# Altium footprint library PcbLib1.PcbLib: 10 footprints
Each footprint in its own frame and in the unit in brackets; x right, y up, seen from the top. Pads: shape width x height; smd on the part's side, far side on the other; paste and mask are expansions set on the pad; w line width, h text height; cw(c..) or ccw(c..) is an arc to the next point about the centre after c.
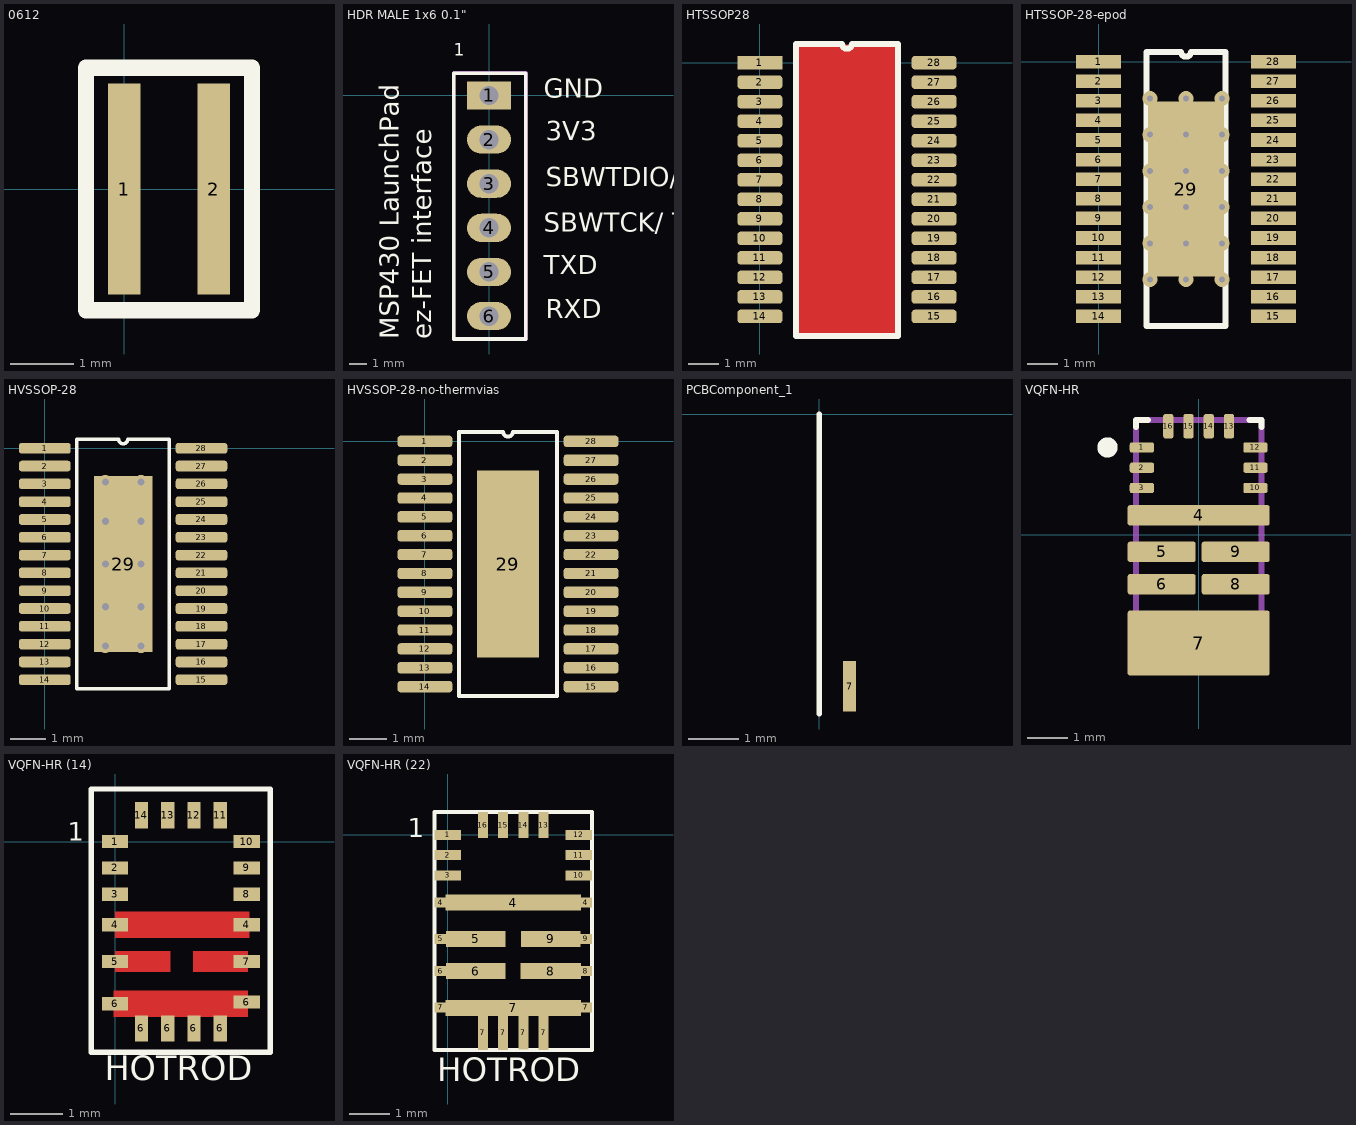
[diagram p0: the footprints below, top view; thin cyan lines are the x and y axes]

## 0612 [mil]
pads (2):
  rect 20x130 smd: 1(0,0) 2(55.12,0)
Top Overlay:
  lines w10: -23.62,-74.8 -23.62,-6.18 -23.62,74.8 78.74,74.8 78.74,-74.8 -23.62,-74.8

## HDR MALE 1x6 0.1" [mm] "WURTH HEADER MALE 1x6"
pads (6):
  rect 2.5x1.6 hole 1.1: 1(0,0)
  oval 2.5x1.6 hole 1.1: 2(0,-2.5) 3(0,-5) 4(0,-7.5) 5(0,-10) 6(0,-12.5)
Top Overlay:
  lines w0.2: -2,-13.8 2.085,-13.8 2.085,1.25 -2,1.25 -2,-13.8
  text "MSP430 LaunchPad / ez-FET interface" at -2.9,-13.8 h1.85
  text "1" at -2,2 h1.2
  text "GND" at 3.1,-0.5 h1.85
  text "3V3" at 3.2,-2.9 h1.85
  text "SBWTDIO/ RST" at 3.2,-5.5 h1.85
  text "SBWTCK/ TEST" at 3.1,-8.1 h1.85
  text "TXD" at 3.1,-10.5 h1.85
  text "RXD" at 3.2,-13 h1.85
Mechanical 29:
  lines w0.2: -2,-13.8 2.1,-13.8 2.1,1.3 -2,1.3 -2,-13.8
  text "1" at -2,2 h1.2

## HTSSOP28 [mm] "HTSSOP28"
pads (28):
  rect 1.5x0.45 smd: 1(0,0)
  rrect50% 1.5x0.45 smd: 2(0,-0.65) 3(0,-1.3) 4(0,-1.95) 5(0,-2.6) 6(0,-3.25) 7(0,-3.9) 8(0,-4.55) 9(0,-5.2) 10(0,-5.85) 11(0,-6.5) 12(0,-7.15) 13(0,-7.8) 14(0,-8.45) 15(5.8,-8.45) 16(5.8,-7.8) 17(5.8,-7.15) 18(5.8,-6.5) 19(5.8,-5.85) 20(5.8,-5.2) 21(5.8,-4.55) 22(5.8,-3.9) 23(5.8,-3.25) 24(5.8,-2.6) 25(5.8,-1.95) 26(5.8,-1.3) 27(5.8,-0.65) 28(5.8,0)
Top Layer:
  rectangle: 1.2,-9.1 4.6,0.6
Top Overlay:
  lines w0.2: 1.2,0.6 1.2,-9.1 4.6,-9.1 4.6,0.6 ; 1.2,0.625 2.738,0.625 ccw(c2.9,0.625) 3.062,0.625 4.6,0.625

## HTSSOP-28-epod [mm]
pads (29):
  rect 1.5x0.45 smd: 1(0,0) 2(0,-0.65) 3(0,-1.3) 4(0,-1.95) 5(0,-2.6) 6(0,-3.25) 7(0,-3.9) 8(0,-4.55) 9(0,-5.2) 10(0,-5.85) 11(0,-6.5) 12(0,-7.15) 13(0,-7.8) 14(0,-8.45) 15(5.8,-8.45) 16(5.8,-7.8) 17(5.8,-7.15) 18(5.8,-6.5) 19(5.8,-5.85) 20(5.8,-5.2) 21(5.8,-4.55) 22(5.8,-3.9) 23(5.8,-3.25) 24(5.8,-2.6) 25(5.8,-1.95) 26(5.8,-1.3) 27(5.8,-0.65) 28(5.8,0)
  rect 2.53x5.8 smd: 29(2.9,-4.225)
via 4.1,-7.225 diameter 0.5 hole 0.2
via 2.9,-7.225 diameter 0.5 hole 0.2
via 1.7,-7.225 diameter 0.5 hole 0.2
via 4.1,-2.425 diameter 0.5 hole 0.2
via 2.9,-2.425 diameter 0.5 hole 0.2
via 1.7,-2.425 diameter 0.5 hole 0.2
via 1.7,-4.825 diameter 0.5 hole 0.2
via 2.9,-4.825 diameter 0.5 hole 0.2
via 4.1,-4.825 diameter 0.5 hole 0.2
via 4.1,-6.025 diameter 0.5 hole 0.2
via 2.9,-6.025 diameter 0.5 hole 0.2
via 1.7,-6.025 diameter 0.5 hole 0.2
via 1.7,-1.225 diameter 0.5 hole 0.2
via 2.9,-1.225 diameter 0.5 hole 0.2
via 4.1,-1.225 diameter 0.5 hole 0.2
via 4.1,-3.625 diameter 0.5 hole 0.2
via 1.7,-3.625 diameter 0.5 hole 0.2
via 2.9,-3.625 diameter 0.5 hole 0.2
Top Overlay:
  lines w0.2: 1.585,-8.775 1.585,0.325 2.738,0.325 ccw(c2.9,0.325) 3.062,0.325 4.215,0.325 4.215,-8.775 1.585,-8.775

## HVSSOP-28 [mm]
pads (29):
  rrect50% 1.45x0.3 smd: 1(0,0) 2(0,-0.5) 3(0,-1) 4(0,-1.5) 5(0,-2) 6(0,-2.5) 7(0,-3) 8(0,-3.5) 9(0,-4) 10(0,-4.5) 11(0,-5) 12(0,-5.5) 13(0,-6) 14(0,-6.5) 15(4.4,-6.5) 16(4.4,-6) 17(4.4,-5.5) 18(4.4,-5) 19(4.4,-4.5) 20(4.4,-4) 21(4.4,-3.5) 22(4.4,-3) 23(4.4,-2.5) 24(4.4,-2) 25(4.4,-1.5) 26(4.4,-1) 27(4.4,-0.5) 28(4.4,0)
  rect 1.65x4.95 smd mask+0.2: 29(2.2,-3.25)
via 2.7,-4.45 diameter 0.4 hole 0.2
via 1.7,-4.45 diameter 0.4 hole 0.2
via 2.7,-2.05 diameter 0.4 hole 0.2
via 1.7,-2.05 diameter 0.4 hole 0.2
via 2.7,-3.25 diameter 0.4 hole 0.2
via 1.7,-3.25 diameter 0.4 hole 0.2
via 2.7,-5.55 diameter 0.4 hole 0.2
via 1.7,-5.55 diameter 0.4 hole 0.2
via 2.7,-0.95 diameter 0.4 hole 0.2
via 1.7,-0.95 diameter 0.4 hole 0.2
Top Layer:
  region: 7.7,-1.05
Top Overlay:
  lines w0.1: 0.9,-6.75 3.5,-6.75 3.5,0.25 2.325,0.25 cw(c2.2,0.25) 2.075,0.25 0.9,0.25 0.9,-6.75

## HVSSOP-28-no-thermvias [mm] "HVSSOP-28 without thermal vias"
pads (29):
  rrect50% 1.45x0.3 smd: 1(0,0) 2(0,-0.5) 3(0,-1) 4(0,-1.5) 5(0,-2) 6(0,-2.5) 7(0,-3) 8(0,-3.5) 9(0,-4) 10(0,-4.5) 11(0,-5) 12(0,-5.5) 13(0,-6) 14(0,-6.5) 15(4.4,-6.5) 16(4.4,-6) 17(4.4,-5.5) 18(4.4,-5) 19(4.4,-4.5) 20(4.4,-4) 21(4.4,-3.5) 22(4.4,-3) 23(4.4,-2.5) 24(4.4,-2) 25(4.4,-1.5) 26(4.4,-1) 27(4.4,-0.5) 28(4.4,0)
  rect 1.65x4.95 smd mask+0.2: 29(2.2,-3.25)
Top Overlay:
  lines w0.1: 0.9,-6.75 3.5,-6.75 3.5,0.25 2.325,0.25 cw(c2.2,0.25) 2.075,0.25 0.9,0.25 0.9,-6.75

## PCBComponent_1 [mm]
pads (1):
  rect 0.25x1 smd: 7(0.6,-5.4)
Top Overlay:
  lines w0.1: 0,-5.95 0,0

## VQFN-HR [mm] "DRV8x44"
pads (16):
  rrect40% 0.6x0.25 smd paste+0 mask+0: 1(-1.4,2.15) 2(-1.4,1.65) 3(-1.4,1.15) 10(1.4,1.15) 11(1.4,1.65) 12(1.4,2.15)
  rrect20% 3.5x0.5 smd paste-1000 mask-1000: 4(0,0.475)
  rrect20% 1.675x0.5 smd paste-1000 mask-1000: 5(-0.913,-0.425) 6(-0.913,-1.225) 8(0.913,-1.225) 9(0.913,-0.425)
  rrect6% 3.5x1.6 smd paste-1000 mask-1000: 7(0,-2.675)
  rrect40% 0.25x0.6 smd paste+0 mask+0: 13(0.75,2.675) 14(0.25,2.675) 15(-0.25,2.675) 16(-0.75,2.675)
Top Overlay:
  circle w0.25: c-2.25,2.15 r0.125
  lines w0.15: -1.55,2.65 -1.55,2.825 -1.25,2.825 ; 1.25,2.825 1.55,2.825 1.55,2.65
Top Paste:
  drawing of 12 lines, arcs and shapes, not listed
Top Solder:
  drawing of 6 lines, arcs and shapes, not listed
M5 Assembly Top:
  lines w0.15: -1.55,-3.275 1.55,-3.275 1.55,2.825 -1.55,2.825 -1.55,-3.275
  text ".Designator" at 0.21,-2.63 h0.5
3D body "IC_DRV8244_VQFN_HR_VQFN-HR16.STEP": height 0.25, standoff 0, extent -1.85,-3.575 1.851,3.075

## VQFN-HR (14) [mm]
pads (20):
  rect 0.5x0.25 smd: 1(0,0) 2(0,-0.5) 3(0,-1) 4(0,-1.58) 4(2.5,-1.58) 5(0,-2.28) 6(0,-3.08) 6(2.5,-3.05) 7(2.5,-2.28) 8(2.5,-1) 9(2.5,-0.5) 10(2.5,0)
  rect 0.25x0.5 smd: 6(0.5,-3.55) 6(1,-3.55) 6(1.5,-3.55) 6(2,-3.55) 11(2,0.5) 12(1.5,0.5) 13(1,0.5) 14(0.5,0.5)
Top Layer:
  rectangle: -0.025,-3.33 2.525,-2.83
  rectangle: 0,-2.48 1.05,-2.08
  rectangle: 0,-1.83 2.55,-1.33
  rectangle: 1.48,-2.48 2.53,-2.08
Top Overlay:
  lines w0.1: -0.45,-4 -0.45,1 2.95,1 2.95,-4 -0.45,-4
  text "1" at -0.9,-0.1 h0.6
  text "HOTROD" at -0.2,-4.7 h0.8
Mechanical 29:
  text "'.Designator'" at 1.65,-3.925 h1.85

## VQFN-HR (22) [mm]
pads (28):
  rect 0.65x0.25 smd: 1(0,0) 2(0,-0.5) 3(0,-1) 10(3.25,-1) 11(3.25,-0.5) 12(3.25,0)
  rect 0.3x0.25 smd: 4(-0.175,-1.675) 4(3.425,-1.675) 5(-0.175,-2.575) 6(-0.175,-3.375) 7(-0.175,-4.275) 7(3.425,-4.275) 8(3.425,-3.375) 9(3.425,-2.575)
  rect 3.35x0.4 smd: 4(1.625,-1.675) 7(1.625,-4.285)
  rect 1.475x0.4 smd: 5(0.695,-2.575) 6(0.695,-3.375) 9(2.555,-2.575)
  rect 0.25x0.85 smd: 7(0.875,-4.9) 7(1.375,-4.9) 7(1.875,-4.895) 7(2.375,-4.9)
  rect 1.49x0.4 smd: 8(2.555,-3.375)
  rect 0.25x0.65 smd: 13(2.375,0.245) 14(1.875,0.245) 15(1.375,0.245) 16(0.875,0.245)
Top Layer:
  pour cut-out: 3.985,1.14
Top Overlay:
  lines w0.1: -0.325,-5.325 -0.325,0.575 3.575,0.575 3.575,-5.325 -0.325,-5.325
  text "1" at -0.995,-0.215 h0.8
  text "HOTROD" at -0.255,-6.295 h1
Mechanical 29:
  text "'.Designator'" at 2.045,-5.035 h1.85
